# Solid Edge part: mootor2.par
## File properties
Author: Indrek
Template: Normal.par
Last saved by: Indrek
Revision: 9
Application: Solid Edge
Density: 7750,000 kg/m^3
Accuracy: 0,990
Material: Stainless Steel, 420
Face Style: Steel
Fill Style: ANSI32(Steel)
Virtual Style: Stainless steel
Coef. of Thermal Exp: 1e-05
Thermal Conductivity: 25.0
Specific Heat: 502.0
Modulus of Elasticity: 19994795300.0
Poission's Ratio: 0.29
Yield Stress: 344737850.0
Ultimate Stress: 655001915.0
Elongation: 0.0
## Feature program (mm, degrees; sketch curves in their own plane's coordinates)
helix protrusion "HelixProtrusion_5"  NumberOfTurns = 6
helix protrusion "HelixProtrusion_6"  NumberOfTurns = 6
sketch for "unnamed RevolvedProtrusion 1" plane through (0, 0, 0) normal (0, 0, 1) x-axis (1, 0, 0)
  line (0, 0) -> (0, 340)
  line (0, 340) -> (-18.9211, 331.8656)
  line (-18.9211, 331.8656) -> (-14.1095, 55.1032)
  bspline degree 3 poles (-14.1095, 55.1032) (-20.1308, 43.3282) (-31.911, 8.0019) (-97.1286, 28.071) (-100.2617, 2.8508) (-100.6788, 0) knots 0 0.3247 0.9293 1 multiplicities 4 1 1 4
  line (-100.6788, 0) -> (0, 0)
revolve "unnamed RevolvedProtrusion 1" add finite 360 deg
swept protrusion "unnamed SweptProtrusion 1"
chamfer "Chamfer_3" setback 6
swept protrusion "unnamed SweptProtrusion 2"
chamfer "Chamfer_5" setback 4
sketch for "ExtrudedCutout_1" plane through (0, 0, 0) normal (0, -1, 0) x-axis (1, 0, 0)
  line (1, 2) -> (0, 2)
  line (0, 2) -> (0, 0)
  line (0, 0) -> (1, 0)
  line (1, 0) -> (1, 2)
extrude "ExtrudedCutout_1" cut finite 2 along -normal
sketch for "ExtrudedCutout_2" plane through (0, 0, 0) normal (0, 0, 1) x-axis (1, 0, 0)
  line (-184.0667, 125.8534) -> (201.3053, 125.8534)
  line (201.3053, 125.8534) -> (201.3053, 388.8121)
  line (201.3053, 388.8121) -> (-184.0667, 388.8121)
  line (-184.0667, 388.8121) -> (-184.0667, 125.8534)
extrude "ExtrudedCutout_2" cut finite 200.4962 symmetric
pattern "unnamed Pattern 1" of "unnamed SweptProtrusion 2", "Chamfer_5"
swept protrusion "unnamed SweptProtrusion 3"
chamfer "unnamed Chamfer 1"
swept protrusion "unnamed SweptProtrusion 4"
chamfer "unnamed Chamfer 2"
sketch for "ExtrudedProtrusion_1" plane through (0, 0, 0) normal (0, -1, 0) x-axis (1, 0, 0)
  circle centre (0, 0) radius 100.6788
extrude "ExtrudedProtrusion_1" add finite 100 along +normal
sketch for "unnamed Cutout 1" #1 plane through (-59.5581, 0, -120.4654) normal (-0.443193, 0, -0.896426) x-axis (0, -1, 0)
  line (7.8913, -35.7053) -> (7.8913, 67.6019)
  line (7.8913, 67.6019) -> (17.8913, 67.6019)
  line (17.8913, 67.6019) -> (17.8913, 34.4746)
  line (17.8913, 34.4746) -> (29.4883, 67.6019)
  line (29.4883, 67.6019) -> (39.4883, 67.6019)
  line (39.4883, 67.6019) -> (39.4883, 41.6471)
  line (60.4184, 64.2947) -> (60.4184, 56.386)
  line (80.4184, 64.2947) -> (60.4184, 64.2947)
  line (80.4184, -35.7053) -> (80.4184, 64.2947)
  line (60.4184, -35.7053) -> (80.4184, -35.7053)
  line (60.4184, -27.7966) -> (60.4184, -35.7053)
  line (39.4883, -13.0577) -> (39.4883, -35.7053)
  line (39.4883, -35.7053) -> (29.4883, -35.7053)
  line (29.4883, -35.7053) -> (29.4883, -0.219)
  line (29.4883, -0.219) -> (17.8913, -35.7053)
  line (17.8913, -35.7053) -> (7.8913, -35.7053)
sketch for "unnamed Cutout 1" #2 plane through (-59.5581, 0, -120.4654) normal (-0.443193, 0, -0.896426) x-axis (0, -1, 0)
extrude "unnamed Cutout 1" cut along -normal
fillet "Round_1" radius 15
swept protrusion "unnamed SweptProtrusion 5"
chamfer "unnamed Chamfer 3"
chamfer "Chamfer_9" setback 2
Other named dimensions: "OffsetSurface_1": Distance = 5 mm | "OffsetSurface_2": Distance = 3.175 mm | "ExtrudedSurface_5": FiniteDepth = 152.7005 mm
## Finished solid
Body 1: sheet body, 1 face, 4 edges, 4 vertices.
  Faces by surface: swept 1
  Edges by curve: line 2, spline 2
Body 2: sheet body, 1 face, 4 edges, 4 vertices.
  Faces by surface: swept 1
  Edges by curve: line 2, spline 2
Body 3: sheet body, 1 face, 2 edges, 0 vertices.
  Faces by surface: cylinder 1
  Edges by curve: circle 2
Body 4: sheet body, 1 face, 2 edges, 0 vertices.
  Faces by surface: cylinder 1
  Edges by curve: circle 2
Body 5: solid body, 58 faces, 142 edges, 84 vertices, 1 internal void.
  Faces by surface: plane 27, spline 18, cone 4, cylinder 4, swept 3, spun 1, torus 1
  Edges by curve: intersection 50, line 42, circle 28, curve on surface 12, ellipse 5, spline 5
Bounding box of the edges (mm; curved faces can reach further): 207.708 x 225.853 x 207.708, from (-103.8538, -100, -103.8538) to (103.8538, 125.8534, 103.8538).
Cylindrical faces by radius (mm): R18.9211 x1, R95.6788 x2, R100.6788 x2, R103.8538 x1
Conical faces (half-angle, radius in mm at the cone's reference point): 0.996 deg R18.9211 x4
Toroidal faces (ring radius, tube radius in mm): R85.6788 r15 x1
Planar faces by outward normal: +x 1, +y 6, +z 1, -x 2, -y 6, -z 1, oblique 10
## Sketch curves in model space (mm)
circle centre (-17.1899, 11.978, 60.2864) radius 5.4097
spline (-17.1899, 11.978, 0) -> (22.5061, 96.9614, 0) -> (-15.3617, 110.3011, 0)
ellipse centre (-71.5545, -52.2134, -114.5344) radii 26.9113, 5.2008
ellipse centre (-72.3723, -52.2134, -114.1301) radii 50, 15.2014 from (-96.8916, -39.4883, -102.0077) through (-116.4534, -49.4623, -92.3364) to (-110.104, -60.4184, -95.4755)
line (-117.1936, -60.4184, -91.9704) -> (-110.104, -60.4184, -95.4755)
line (-117.1936, -80.4184, -91.9704) -> (-117.1936, -60.4184, -91.9704)
line (-27.551, -80.4184, -136.2898) -> (-117.1936, -80.4184, -91.9704)
line (-27.551, -60.4184, -136.2898) -> (-27.551, -80.4184, -136.2898)
line (-34.6406, -60.4184, -132.7847) -> (-27.551, -60.4184, -136.2898)
ellipse centre (-72.3723, -52.2134, -114.1301) radii 50, 15.2014 from (-34.6406, -60.4184, -132.7847) through (-28.8339, -48.6024, -135.6555) to (-47.8529, -39.4883, -126.2525)
line (-47.8529, -39.4883, -126.2525) -> (-27.551, -39.4883, -136.2898)
line (-27.551, -39.4883, -136.2898) -> (-27.551, -29.4883, -136.2898)
line (-27.551, -29.4883, -136.2898) -> (-59.3618, -29.4883, -120.5625)
line (-59.3618, -29.4883, -120.5625) -> (-27.551, -17.8913, -136.2898)
line (-27.551, -17.8913, -136.2898) -> (-27.551, -7.8913, -136.2898)
line (-27.551, -7.8913, -136.2898) -> (-120.1583, -7.8913, -90.5047)
line (-120.1583, -7.8913, -90.5047) -> (-120.1583, -17.8913, -90.5047)
line (-120.1583, -17.8913, -90.5047) -> (-90.4621, -17.8913, -105.1865)
line (-90.4621, -17.8913, -105.1865) -> (-120.1583, -29.4883, -90.5047)
line (-120.1583, -29.4883, -90.5047) -> (-120.1583, -39.4883, -90.5047)
line (-120.1583, -39.4883, -90.5047) -> (-96.8916, -39.4883, -102.0077)
spline (0, 7.05, 59.2407) -> (0, 70.572, 56.5178) -> (0, 96.911, 15.1873)
spline (-60.6001, 1.2283, 29.9607) -> (-42.6603, 64.4288, 21.0913) -> (0.1963, 102.2136, -0.097)
spline (-60.0834, 0, 0) -> (-54.9444, 52.7431, 0) -> (-7.9741, 85.909, 0)
circle centre (-50.3394, 0, -4.1585) radius 13.3441
circle centre (-81.8073, 0, 20.2066) radius 1.8398
circle centre (-81.8073, 0, 32.3698) radius 3.5312
circle centre (-75.1371, 0, 45.7101) radius 6.002
circle centre (-70.0364, 0, 14.7135) radius 9.2601
circle centre (-58.2656, 0, 31.5851) radius 7.7881
line (-18.9211, 331.8656, 0) -> (-14.1095, 55.1032, 0)
spline (-14.1095, 55.1032, 0) -> (-54.5554, 20.3601, 0) -> (-100.6788, 0, 0)
line (-100.6788, 0, 0) -> (0, 0, 0)
line (0, 0, 0) -> (0, 340, 0)
line (0, 340, 0) -> (-18.9211, 331.8656, 0)
circle centre (0, 33.086, 18.7831) radius 12.6697
line (0, 0, 0) -> (0, 340, 0)
line (0, 13.7097, 3.2006) -> (0, 13.7097, 18.9211)
line (0, 13.7097, 18.9211) -> (0, 6.0323, 18.9211)
line (0, 6.0323, 18.9211) -> (0, 6.0323, 3.2006)
line (0, 6.0323, 3.2006) -> (0, 13.7097, 3.2006)
line (0, 0, -100.6788) -> (0, 140, -100.6788)
line (0, 0, 100.6788) -> (0, 140, 100.6788)
line (0, 0, 0) -> (0, 340, 0)
circle centre (0, 0, 0) radius 100.6788
circle centre (0, 0, 0) radius 38.8474
line (1, 0, 0) -> (1, 0, 2)
line (1, 0, 2) -> (0, 0, 2)
line (0, 0, 2) -> (0, 0, 0)
line (0, 0, 0) -> (1, 0, 0)
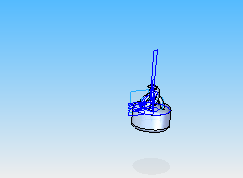
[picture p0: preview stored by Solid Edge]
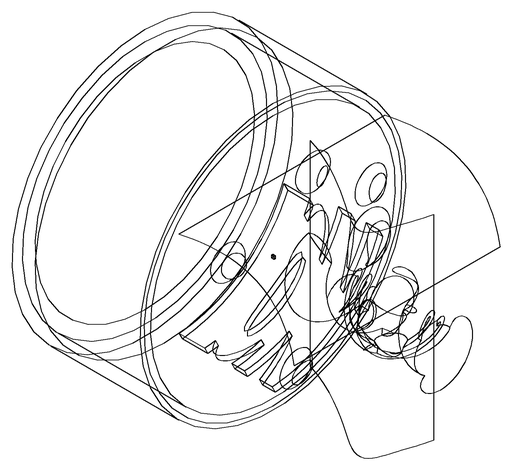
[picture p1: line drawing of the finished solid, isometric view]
